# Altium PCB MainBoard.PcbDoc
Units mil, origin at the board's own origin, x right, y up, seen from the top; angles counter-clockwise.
Board outline 4000 x 1600 mil, 2 copper layers (Top Layer, Bottom Layer); 19 components, 15 nets, 57 pads, 0 vias.
Unrouted connection lines stored in the file: 3.
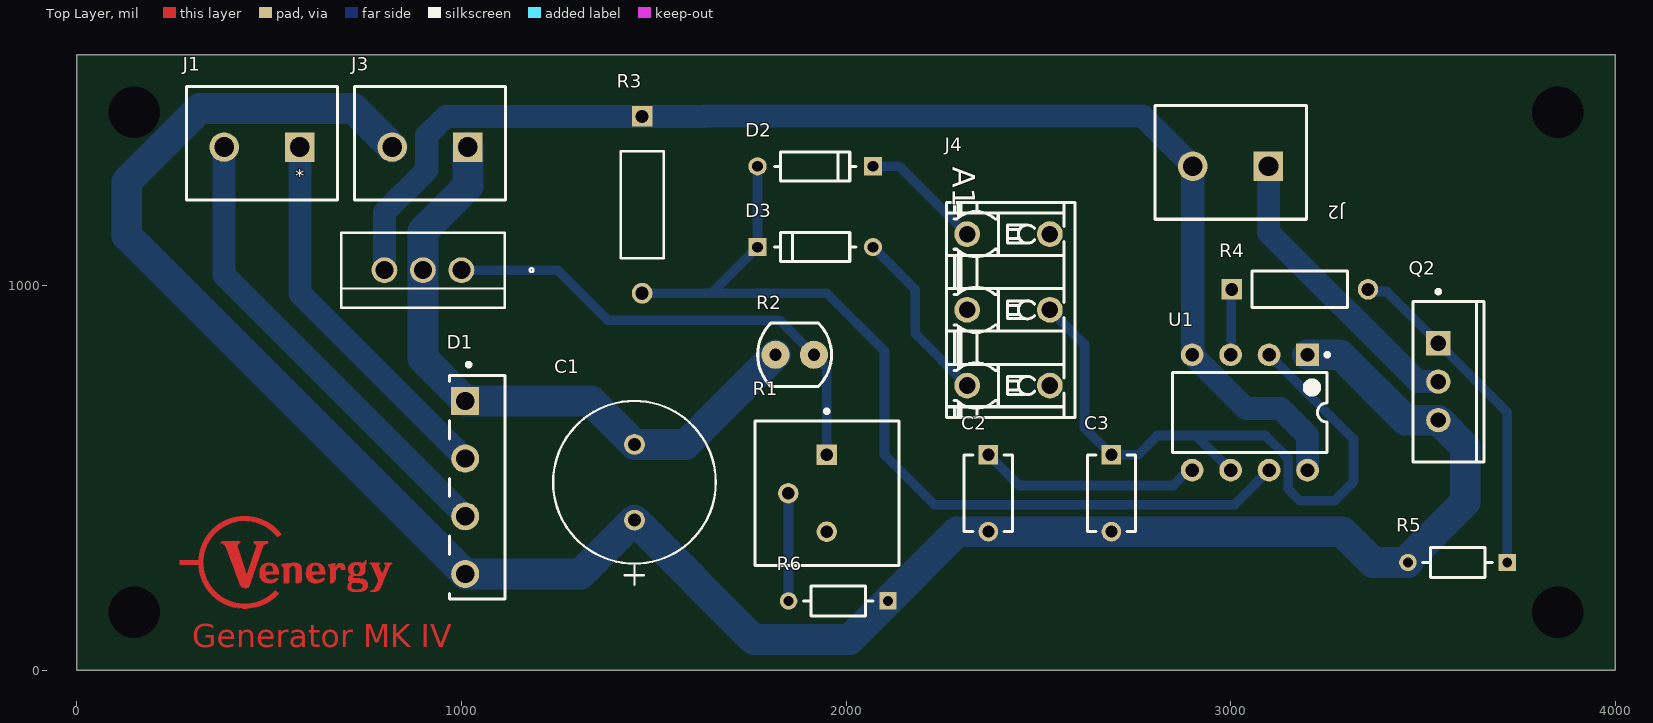
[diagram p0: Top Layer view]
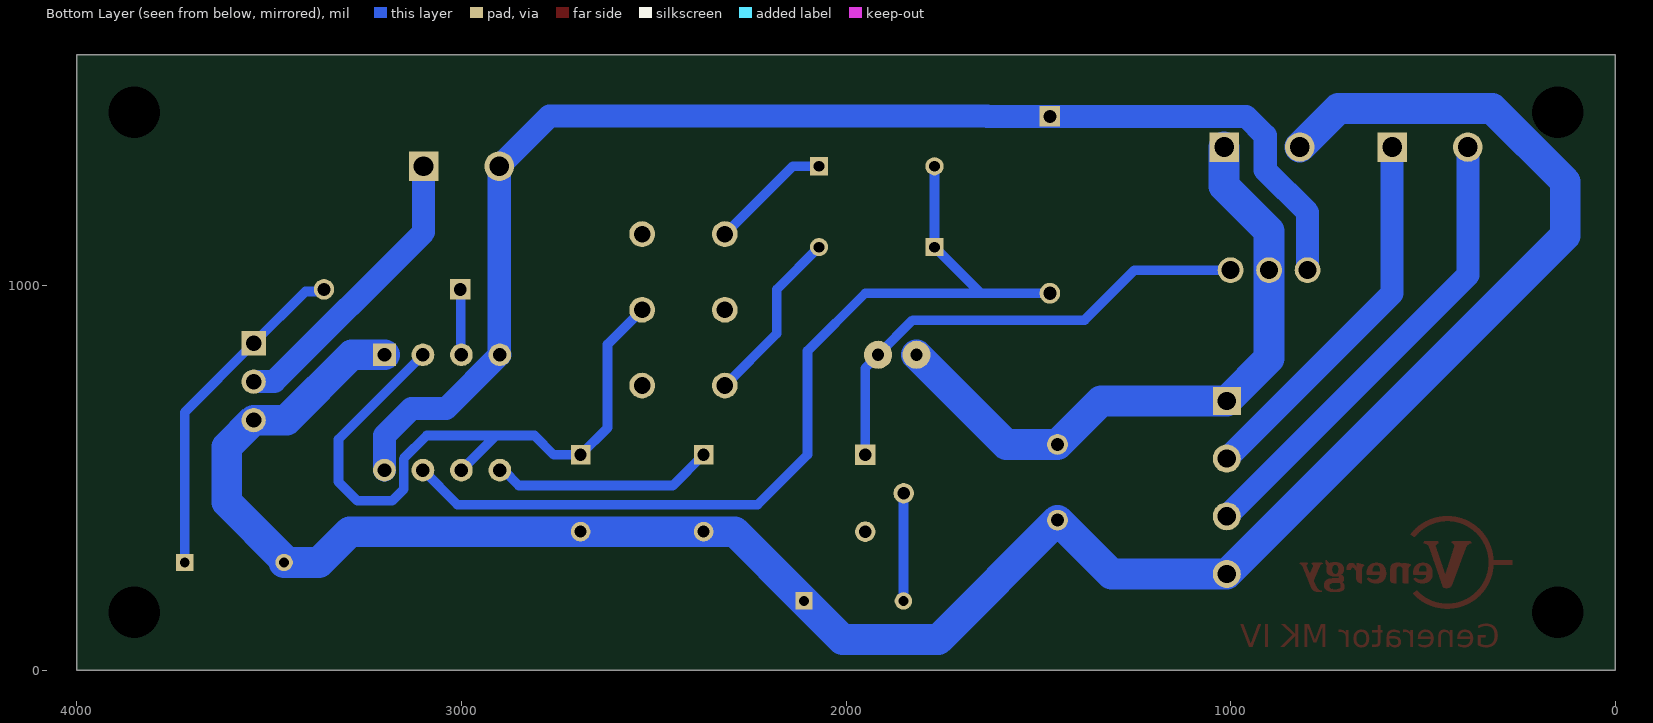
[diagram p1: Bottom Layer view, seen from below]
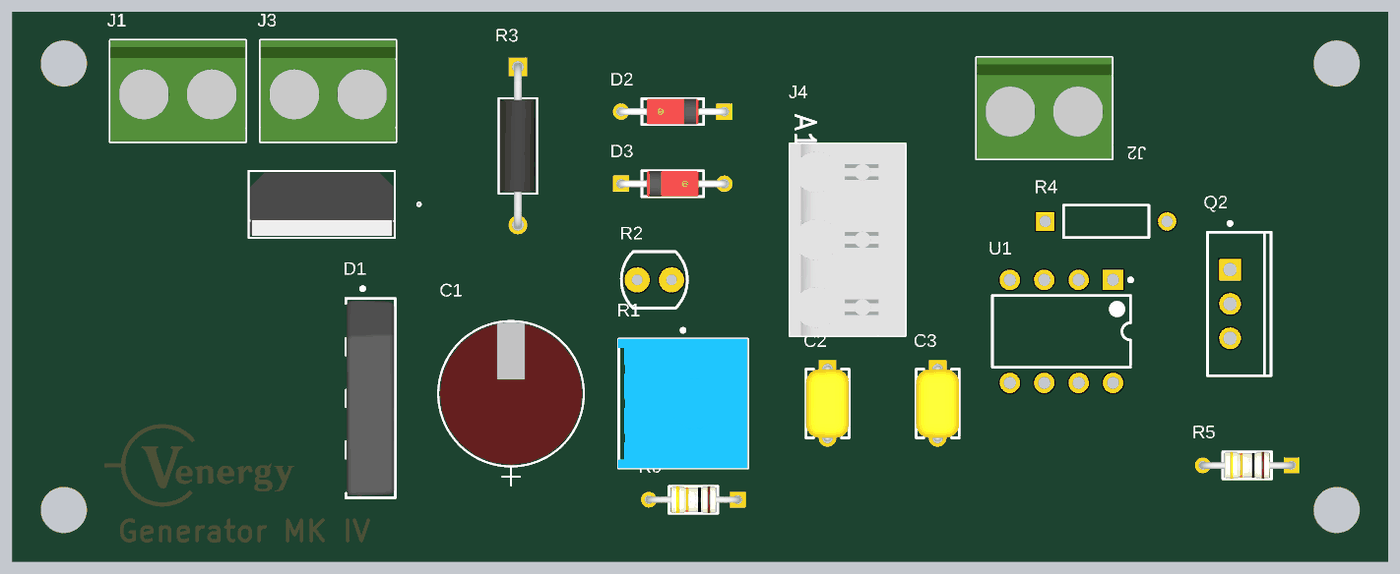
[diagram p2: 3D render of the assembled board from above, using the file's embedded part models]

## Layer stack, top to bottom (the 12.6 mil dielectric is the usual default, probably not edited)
Top Solder: solder mask 1, SM-001, Dk 4
Top Layer: signal copper 1.378
Dielectric 1: dielectric 12.6, FR-4, Dk 4.8
Bottom Layer: signal copper 1.378
Bottom Solder: solder mask 1, SM-001, Dk 4

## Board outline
0,0 4000,0 4000,1600 0,1600

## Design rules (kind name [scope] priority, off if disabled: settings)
Clearance [All] p1: gap=0 ignorepadtopadclearanceinfootprint=FALSE
PolygonConnect [All] p1: connectstyle=Relief reliefconductorwidth=10 reliefentries=4 polygonreliefangle="90 Angle" airgapwidth=10
RoomDefinition Rectifier_Charger_Board [InComponentClass('Rectifier_Charger_Board')] p1: confinementstyle=ConfineIn formatcopy=TRUE lockcomponents=FALSE outline 0,0 4000,0 4000,1600 0,1600
RoutingVias [All] p1: holewidth=28 width=50 viastyle="Through Hole" minholewidth=28 minwidth=50 maxholewidth=28 maxwidth=50
SolderMaskExpansion [All] p1: expansion=4 istentingtop=FALSE
Width Input1 [InNet('Pri1')] p1: maxlimit=65 minlimit=25 preferedwidth=60
Width Input2 [InNet('Pri2')] p2: maxlimit=65 minlimit=25 preferedwidth=60
Width Ground [InNet('GND')] p3: maxlimit=85 minlimit=10 preferedwidth=80
Width Power [InNet('Out')] p4: maxlimit=85 minlimit=10 preferedwidth=80
Width DC [InNet('DC')] p5: maxlimit=85 minlimit=10 preferedwidth=60
Width Load [InNet('Load')] p6: maxlimit=85 minlimit=10 preferedwidth=60
Width [All] p7: maxlimit=30 minlimit=25 preferedwidth=25
30 further rules are at their usual default settings.

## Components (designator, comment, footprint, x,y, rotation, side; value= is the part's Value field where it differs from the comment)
* "IRF9Z34NPBF" IRF9Z34NPBF-Footprint-1 1000,1040 r180 top
C1 "16YXJ1000MT810X16" 16YXJ1000MT810X16-Footprint-1 1450,390 r90 top
C2 "C322C104K5R5TA" FP-C322C104K5R5TA-MFG 2370,460 r270 top
C3 "C322C104K5R5TA" FP-C322C104K5R5TA-MFG 2690,460 r270 top
D1 "KBP206G" FP-KBP-MFG 1041.5,475.59 r270 top value=25pF
D2 "1N4148" FP-017AG-MFG 1920,1310 r180 top
D3 "1N4148" FP-017AG-MFG 1920,1100 r0 top
J1 "Generator Connector" 691137710002 481.57,1369.84 r180 top
J2 "LED Connector" 691137710002 3000,1320 r180 top
J3 "Battery Connector" 691137710002 918.43,1369.84 r180 top
J4 "Pot Connector" LSF_SMT_5_00_180_03 2428.43,936.85 r270 top
Q2 "IRF520NPBF" INTR-TO-220AB-3 3540,750 r0 top
R1 "3386P-1-104LF" BOUR-3386P 1900,460 r270 top
R2 "VT90N1" EXCE-VT90N1 1866.57,820 r180 top
R3 "CFR-25JB-52-1K" "New footprint 1" 1470,1440 r270 top
R4 "MFR-25FBF52-1K" RESA60-630X240 3180,990 r0 top
R5 "CF18JT10K0" FP-CF18-MFG 3590,280 r180 top value=10kR
R6 "CF18JT10K0" FP-CF18-MFG 1980,180 r180 top value=10kR
U1 "NE555P" P0008A 3050,670 r270 top

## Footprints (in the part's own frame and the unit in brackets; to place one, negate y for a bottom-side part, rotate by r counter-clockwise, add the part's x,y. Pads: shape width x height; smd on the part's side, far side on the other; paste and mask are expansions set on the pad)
16YXJ1000MT810X16-Footprint-1 [mil]
  round 54 hole 34 mask+0: 1(0,0) 2(196.85,0)
  silkscreen extent -168,-212 310,212, body extent -108,-206 306,206, height 552
691137710002 [mm] "Horizontal Cable Entry with Pressure Clamp, pitch 5mm, 02p"
  rect 1.95x1.95 hole 1.3: 1(-2.5,0.25)
  round 1.95 hole 1.3: 2(2.5,0.25)
  silkscreen extent -5,-3.75 5,3.75, body extent -5,-3.75 5,3.75, height 11.6
BOUR-3386P [mm] "THD, 3-Leads, Body 9.53x9.53mm, Pitch 2.54mm"
  rect 1.35x1.35 hole 0.85: 1(-2.54,1.27)
  round 1.35 hole 0.85: 2(0,-1.27) 3(2.54,1.27)
  silkscreen extent -5.54,-3.48 4.76,6.05, body extent -4.79,-3.52 4.79,6.06, height 4.95
EXCE-VT90N1 [mil] "THD, 2-Leads, Body Width 4.17mm (Max), Height 2.29mm"
  round 73 hole 31.5: 1(-50,0) 2(50,0)
  silkscreen extent -96,-82 96,82, body extent -96,-82 96,82, height 90
FP-017AG-MFG [mm]
  rect 1.2x1.2 hole 0.7 paste-1000 mask+0: 1(-3.813,0)
  round 1.2 hole 0.7 paste-1000 mask+0: 2(3.813,0)
  silkscreen extent -2.68,-0.95 2.68,0.95, body extent -4.51,-1.05 4.51,1.05, height 0.25
FP-C322C104K5R5TA-MFG [mm]
  rect 1.3x1.3 hole 0.8 paste-1000 mask+0: 1(-2.54,0)
  round 1.3 hole 0.8 paste-1000 mask+0: 2(2.54,0)
  silkscreen extent -2.54,-1.59 2.54,1.59, body extent -3.29,-1.69 3.29,1.69, height 0.25
FP-CF18-MFG [mm]
  rect 1.15x1.15 hole 0.65 paste-1000 mask+0: 1(-3.28,0)
  round 1.15 hole 0.65 paste-1000 mask+0: 2(3.28,0)
  silkscreen extent -2.3,-1 2.3,1, body extent -3.96,-1.1 3.96,1.1, height 0.25
FP-KBP-MFG [mm]
  rect 1.85x1.85 hole 1.2 paste-1000 mask+0: 1(-5.7,-0.8)
  round 1.85 hole 1.2 paste-1000 mask+0: 2(-1.89,-0.8) 3(1.92,-0.8) 4(5.73,-0.8)
  silkscreen extent -8.22,-1.83 7.37,1.83, body extent -7.47,-1.92 7.47,1.92, height 0.25
INTR-TO-220AB-3 [mm] "FM, 3-Leads, Body 10.55x4.7mm, Pitch 2.54mm"
  rect 1.6x1.6 hole 1: 1(0,2.54)
  round 1.6 hole 1: 2(0,0) 3(0,-2.54)
  silkscreen extent -1.67,-5.3 3.03,6.07, body extent -1.67,-5.28 3.03,5.28, height 19.3
IRF9Z34NPBF-Footprint-1 [mil]
  round 67 hole 47 mask+0: 1(0,0) 2(100,0) 3(200,0)
  silkscreen extent -188,-98 312,98, body extent -108,-93 308,93, height 620
LSF_SMT_5_00_180_03 [mm] "OMNIMATE Signal - Serie LSF  LSF-SMT 5.00/03/180 3.5"
  round 1.7 hole 1.1: A1(-5,2.58) A1(-5,-2.88) A2(0,2.58) A2(0,-2.88) A3(5,2.58) A3(5,-2.88)
  silkscreen extent -7.1,-4.25 7.1,4.25, body extent -7.1,-4.25 7.1,4.25, height 13.61
"New footprint 1" [mil]
  rect 54x54 hole 34 mask+0: 1(0,0)
  round 54 hole 34 mask+0: 2(460,0)
  silkscreen extent 91,-56 369,56, body extent -12,-51 472,51, height 102
P0008A [mm] "DIP, 8-Leads, Body 10.15x6.6mm, Pitch 2.54mm"
  rect 1.5x1.5 hole 0.9: 1(-3.81,3.81)
  round 1.5 hole 0.9: 2(-3.81,1.27) 3(-3.81,-1.27) 4(-3.81,-3.81) 5(3.81,-3.81) 6(3.81,-1.27) 7(3.81,1.27) 8(3.81,3.81)
  silkscreen extent -3.93,-5.1 2.65,5.24, body extent -3.95,-5.07 3.95,5.07, height 5.08
RESA60-630X240 [mm] "Axial Resistor, 2-Leads, Dia 2.4mm, Body Length 6.3mm"
  rect 1.35x1.35 hole 0.85: 1(-4.5,0)
  round 1.35 hole 0.85: 2(4.5,0)
  silkscreen extent -3.15,-1.2 3.15,1.2, body extent -3.15,-1.2 3.15,1.2, height 2.4

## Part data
*: library part CMP-013-00034-5, "Mosfet, Power; P-ch; Vdss -55V; Rds(on) 0.1 Ohm; Id -19A; TO-220AB; Pd 68W; Vgs +/-20V"
C1: library part CMP-001-00083-1, "Cap Aluminum Lytic 1000uF 16V 20% (10 X 16mm) Radial 5mm 1210mA 10000h 105°C Ammo", Capacitance=1mF, Max Operating Temperature=105°C, Min Operating Temperature=-40°C, Package Quantity=500, Ripple Current=1.21A, Tolerance=20%, Voltage Rating=16V
C2 C3: library part CMP-03020-034661-1, "CAP CER 0.1UF 50V X7R RADIAL", Capacitance=100nF, Case/Package=Radial, Dielectric=X7R, Dielectric Material=Ceramic, Max Operating Temperature=125°C, Min Operating Temperature=-55°C, Package Quantity=500, Tolerance=10%, Voltage=50V
D1: library part CMP-12791-000035-1, "BRIDGE RECT 1PHASE 600V 2A KBP", Capacitance=25pF, Forward Current=2A, Manufacturer="Diodes Inc.", Max Junction Temp=+150°C, Max Repetitive Reverse Voltage=600V, Max Surge Forward Current=65A, Package=KBP, Peak Reverse Current=5uA, Temperature="-65°C to +150°C", Temperature Range Low=-65°C
D2 D3: library part CMP-07163-000046-1, "DIODE GEN PURP 100V 200MA DO35", Average Rectified Current=200mA, Capacitance=4pF, Case/Package=DO-35, Current=4A, Forward Current=300mA, Forward Voltage=1V, Max Forward Surge Current (Ifsm)=1A, Max Operating Temperature=175°C, Max Power Dissipation=500mW, Max Repetitive Reverse Voltage (Vrrm)=100V, Max Reverse Current=5uA, Min Operating Temperature=-65°C, Package Quantity=2000
J1 J2 J3: library part CMP-1502-03324-1, "Series 1377 - 5.00 mm Horizontal Entry with Pressure Clamp WR-TBL, 2 pin", Manufacturer="Wurth Elektronik", Operating Temperature=-30to120degC, Package Reference=691137710002
J4: library part CMP-1559-02314-1, "OMNIMATE Signal - series LSF", Colour=Black, Manufacturer=Weidmueller, PartNumber=1825970000, Rated_current_min_no_of_poles_TU_20_deg_C="19 A", Rated_current_use_group_B_UL_1059="12 A", Rated_voltage_for_surge_voltage_class_pollution_degree_II_2="500 V", Rated_voltage_use_group_B_UL_1059="300 V", UL_94_flammability_rating=V-0
Q2: library part CMP-2100-03647-1, "HEXFET(R) Power MOSFET, 100 V, 9.7 A, 0.2 Ohm, -55 to 175 degC, 3-Pin FM (TO-220AB), RoHS, Tube", Case/Package=TO-220AB, Continuous Drain Current (ID)=9.7A, Drain to Source Breakdown Voltage=100V, Drain to Source Resistance=200mOhm, Gate to Source Voltage (Vgs)=20V, Input Capacitance=330pF, Manufacturer="International Rectifier", Max Operating Temperature=175degC, Max Power Dissipation=48W, Min Operating Temperature=-55degC, Package Description="3-Pin Flange Mount, Body 4.445 x 10.415 mm, Pitch 2.54 mm", Package Quantity=50
R1: library part CMP-2000-05592-1, "Square Trimpot(R) Trimming Potentiometer, 100 KOhm, +/- 10%, 0.5 W, -55 to 125 degC, 3-Pin THD, RoHS, Tube", Manufacturer=Bourns, Manufacturer Series=3386, Maximum Operating Temperature=125C, Minimum Operating Temperature=-55C, Operating Temperature-Max (Cel)=125, Operating Temperature-Min (Cel)=-55, Package=RectangularPackage, Package Description="3-Pin Through Hole Device, Body 9.53 x 9.53 mm, Pitch 2.54 mm", Package Reference=3386P, Power Rating=1/2W, Rated Power Dissipation (P) (W)=0.5, Rated Temperature (Cel)=85, Resistance (ohm)=100000, Resistance Law=Linear, Resistance Value=100KOhm, Resistive Element Material=Cermet, Temperature Coefficient=100ppm/C, Tolerance=10%, Tolerance (%)=10
R2: library part CMP-2000-07406-1, "Photoconductive Resistor, 200 kOhm, 100 V, 80 mW, -40 to 75 degC, 2-Pin THD, RoHS", Dark Resistance=200kohm, Manufacturer="Excelitas Technology", Operating Temperature Max=75°C, Operating Temperature Min=-40°C, Package Description="2-Pin Through Hole Device, Body Width 4.17 mm (Max), Height 2.29 mm", Power Rating=80mW, Resistance @ Lux=12kohm, Resistor Case Style=-, Voltage Rating=100V
R3: library part CMP-009-00177-2, "Res Carbon Film 1K Ohm 5% 1/4W -350ppm/°C to 350ppm/°C Conformal AXL Thru-Hole Bulk", Max Operating Temperature=155°C, Max Power Dissipation=250mW, Min Operating Temperature=-55°C, Resistance=1kR, Tolerance=5%
R4: library part CMP-1659-00075-1, "Axial Resistor, 1 KOhm, +/- 1%, 250 mW, -55 to 155 degC, 2-Pin THD, RoHS, Bulk", Case\Package=Axial, Max Operating Temperature="155 degC", Min Operating Temperature="-55 degC", Package Quantity=200, Power Rating="250 mW", Resistance=1kR, Tolerance=1%, Voltage Rating="250 V"
R5 R6: library part CMP-26528-000002-1, "RES 10K OHM 1/8W 5% CF AXIAL", Manufacturer="Stackpole Electronics", Package=CF18, Power Rating=0.125W, Resistance=10kΩ, Temperature="-55°C to +155°C", Temperature Coefficient=0-500ppm/°C, Temperature Range High=+155°C, Temperature Range Low=-55°C, Tolerance=5%, Voltage Rating=250V
U1: library part CMP-2000-04954-1, "Precision Timer, 4.5 to 16 V, 0 to 70 degC, 8-Pin DIP, Pb-Free, Tube", Manufacturer=TexasInstruments, Maximum High Level Output Current=-200mA, Maximum Low Level Output Current=200mA, Operating Supply Voltage=5, Package=8PDIP, Package Description="8-Pin Double In-line Package, Body 9.59 x 6.35 mm, Pitch 2.54 mm", Package Reference=P8

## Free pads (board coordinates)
  round 62.99 hole 133.86: 3(150,150) 3(150,1450) 3(3850,150) 3(3850,1450)

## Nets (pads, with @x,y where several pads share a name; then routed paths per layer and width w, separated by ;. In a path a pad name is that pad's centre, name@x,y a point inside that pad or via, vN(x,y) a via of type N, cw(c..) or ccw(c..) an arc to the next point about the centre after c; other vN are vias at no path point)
DC: *.3 J2.2 R3.1 U1.4 U1.8 | length 3429.8
  Bottom Layer w60: *.3 800,1190 910,1300 910,1390 960,1440 R3.1 1632.83,1440 1633.28,1440.45 2771.28,1440.45 J2.2 2901.57,821.57 U1.4 3040,680 3130,680 3200,610 U1.8
GND: C1.1 C2.2 C3.2 D1.4 J3.2 Q2.3 R5.2 R6.1 U1.1 | length 5852.2
  Bottom Layer w80: J3.2 720,1460 320,1460 130,1270 130,1130 D1.4 1310,250 C1.1 1760,80 2009.13,80 R6.1 2289.13,360 C2.2 3290,360 3370,280 R5.2 3460.87,287.72 3610,436.85 3610,580 Q2.3 3455,650 3285,820 U1.1
Load: J2.1 Q2.2 | length 774.8
  Bottom Layer w60: J2.1 3098.43,1138.73 3486.58,750.57 3539.43,750.57 Q2.2 Q2.2@3540.81,750
Net*_1: *.1 R1.1 R2.1 | length 1281.5
  Bottom Layer w15: R2.1@1916.57,818.84 R2.1
  Bottom Layer w25: *.1 1250,1040 1380,910 1826.57,910 R2.1 ; R2.1@1916.57,818.84 1950,785.41 R1.1
NetC2_1: C2.1 U1.5 | length 579.7
  Bottom Layer w25: C2.1 2450,480 2850.78,480 2890.78,520 U1.5
NetC3_1: C3.1 J4.A2 U1.2 U1.6 | length 1779.9
  Bottom Layer w25: J4.A2@2530,936.85 2620,846.85 2620,630 C3.1 2760,560 2810,610 2910,610 ; U1.6 2910,610 ; U1.2 3319.64,600.36 3319.64,489.64 3270,440 3180,440 3150,470 3150,550 3090,610 2910,610
NetD2_1: D2.1 J4.A1 | length 317.9
  Bottom Layer w25: D2.1 2138.74,1310 J4.A1@2315.04,1133.7
NetD2_2: D2.2 D3.1 R3.2 U1.7 | length 2432.9
  Bottom Layer w25: R3.2 1650,980 ; D2.2 D3.1 1650,980.12 1650,980 ; U1.7 3010,430 2230,430 2100,560 2100,830 1950,980 1650,980
NetD3_2: D3.2 J4.A3 | length 461.4
  Bottom Layer w25: D3.2 2180,990.12 2180,875.04 J4.A3@2315.04,740
NetQ2_1: Q2.1 R4.2 R5.1 | length 885
  Bottom Layer w25: R4.2 3362.55,984.61 3405.39,984.61 Q2.1 3719.13,670.87 R5.1
NetR1_2: R1.2 R6.2 | length 280.4
  Bottom Layer w25: R1.2 1850.43,459.57 1850.43,180.43 R6.2
NetR4_1: R4.1 U1.3 | length 171.2
  Bottom Layer w25: U1.3 3001.42,821.42 3001.42,988.58 R4.1
Out: *.2 C1.2 D1.1 J3.1 R2.2 | length 1704
  Bottom Layer w80: J3.1 1016.85,1258.43 900,1141.57 *.2 900,810 D1.1 1336.85,700 C1.2 1583.43,586.85 R2.2
Pri1: D1.2 J1.1 | length 988.1
  Bottom Layer w60: J1.1 580,980 D1.2
Pri2: D1.3 J1.2 | length 1223.1
  Bottom Layer w60: J1.2 383.15,1026.85 D1.3 D1.3@1006.53,400
pads on no net: R1.3

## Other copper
Top Layer:
  region: 537 vertices and 2 holes, not listed, extent 703.94,203.42 756.71,285.94
  region: 249 vertices and 0 holes, not listed, extent 531.46,226.44 584.94,279.21
  region: 275 vertices and 0 holes, not listed, extent 652.94,226.44 698.27,278.5
  region: 389 vertices and 1 holes, not listed, extent 475.15,226.08 525.08,278.85
  region: 973 vertices and 0 holes, not listed, extent 374.56,213.33 497.81,335.17
  region: 2484 vertices and 0 holes, not listed, extent 267.25,160.21 531.81,399.98
  region: 389 vertices and 1 holes, not listed, extent 595.92,226.08 645.85,278.85
  region: 605 vertices and 0 holes, not listed, extent 760.96,203.42 820.46,278.85
  text "Generator MK IV" at 300,60 h60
